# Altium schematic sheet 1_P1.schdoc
size 431 x 309 mm; Symbol: Sheet-Symbol_A3; Device: Sheet-Symbol_A3; Company: 嘉立创EDA; Version: V1.0; Page Size: A3; @Project Name: 辉光管_2024.2.16; @Page Count: 1; @Update Date: 2024-06-18; @Create Date: 2024-06-18; @Schematic Name: Schematic6; @Page No: 1; @Page Name: P1
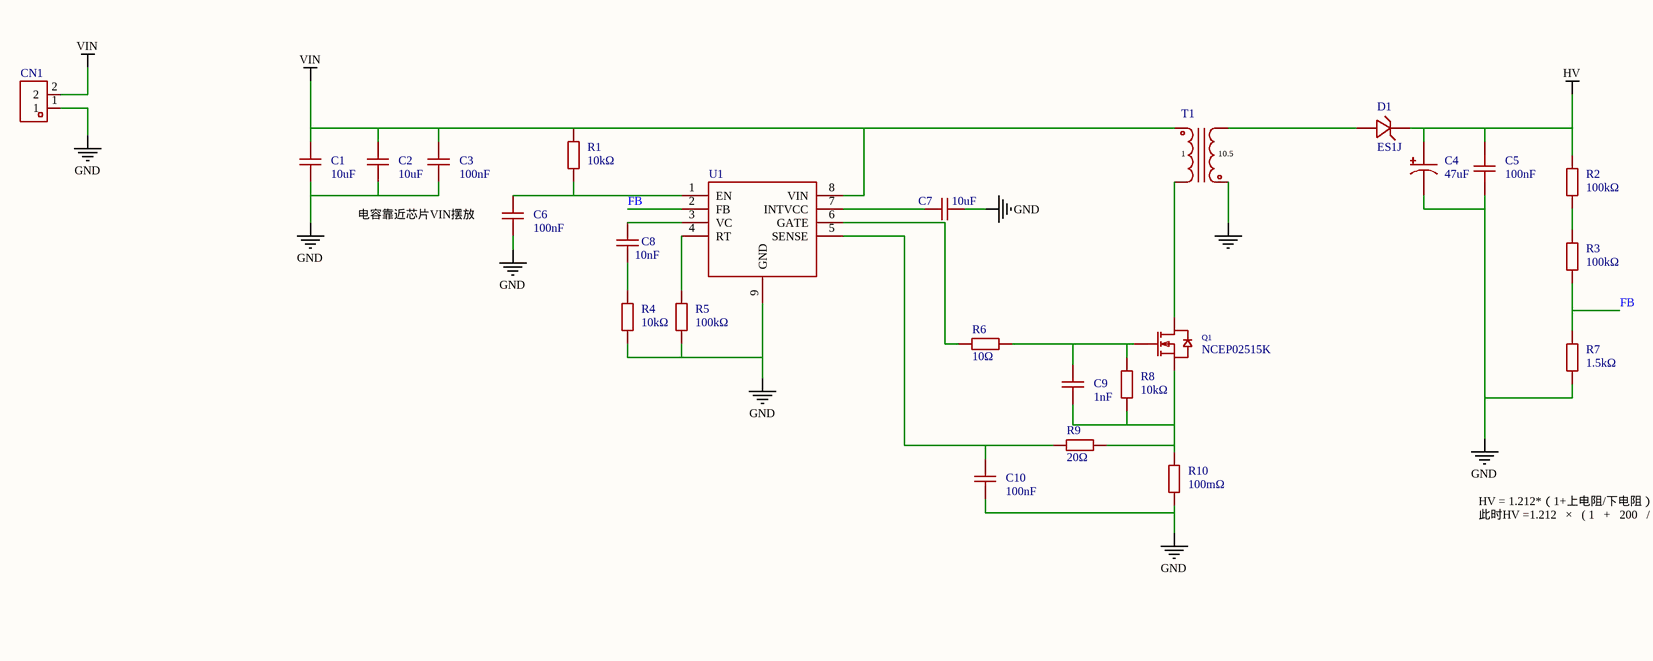
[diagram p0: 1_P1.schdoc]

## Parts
C1  10uF  [C0805]  (value not drawn)
C2  10uF  [C0805]  (value not drawn)
C3  100nF  [C0603]  (value not drawn)
C4  47uF  [CAP-TH_BD12.5-P5.00-D0.6-FD]  (value not drawn)
C5  100nF  [C1206]  (value not drawn)
C6  100nF  [C0603]  (value not drawn)
C7  10uF  [C0805]  (value not drawn)
C8  10nF  [C0603]  (value not drawn)
C9  1nF  [C0603]  (value not drawn)
C10  100nF  [C0603]  (value not drawn)
CN1  ZX-XH2.54-2PZZ  [CONN-TH_2P-P2.50_HX25003-2A]  (value not drawn)
D1  ES1J  [SMA_L4.4-W2.8-LS5.4-RD]  (value not drawn)
Q1  NCEP02515K  [TO-252-3_L6.6-W6.1-P4.58-LS10.1-BR-2]  (value not drawn)
R1  10kΩ  [R0603]  (value not drawn)
R2  100kΩ  [R1206]  (value not drawn)
R3  100kΩ  [R1206]  (value not drawn)
R4  10kΩ  [R0603]  (value not drawn)
R5  100kΩ  [R0603]  (value not drawn)
R6  10Ω  [R0603]  (value not drawn)
R7  1.5kΩ  [R0805]  (value not drawn)
R8  10kΩ  [R0603]  (value not drawn)
R9  20Ω  [R0603]  (value not drawn)
R10  100mΩ  [R1206]  (value not drawn)
T1  TTRN-060S-013-T  [TTRN-060S-013]  (value not drawn)
U1  ASP3756  [ESOP-8_L4.9-W3.9-P1.27-LS6.0-BL-EP4.2]  (value not drawn)

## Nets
GND: C1.1 C2.1 C3.1 C4.2 C5.1 C6.1 C7.2 C10.1 CN1.1 R4.1 R5.1 R7.1 R10.1 T1.3 U1.9(GND)
HV: C4.1 C5.2 D1.1(C) R2.1
VIN: C1.2 C2.2 C3.2 CN1.2 R1.2 T1.1 U1.8(VIN)
FB: R3.2 R7.2 U1.2(FB)
NetC6_2: C6.2 R1.1 U1.1(EN)
NetC7_1: C7.1 U1.7(INTVCC)
NetC8_1: C8.1 R4.2
NetC8_2: C8.2 U1.3(VC)
NetC9_1: C9.1 Q1.3(S) R8.1 R9.2 R10.2
NetC9_2: C9.2 Q1.1(G) R6.2 R8.2
NetC10_2: C10.2 R9.1 U1.5(SENSE)
NetD1_2: D1.2(A) T1.2
NetQ1_2: Q1.2(D) T1.5
NetR2_2: R2.2 R3.1
NetR5_2: R5.2 U1.4(RT)
NetR6_1: R6.1 U1.6(GATE)

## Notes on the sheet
- 电容靠近芯片VIN摆放
- HV = 1.212*（1+上电阻/下电阻）
  此时HV =1.212   ×   ( 1   +   200   /   1.5 ) = 162.712

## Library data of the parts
C1 C2 C7 = 0805X106K250NT: 容值:10uF;精度:±10%;额定电压:25V;材质(温度系数):X5R;; Manufacturer: FH(风华); Add into BOM: yes; Tolerance: ±10%; Voltage Rated: 25V; Temperature Coefficient: X5R
C3 C6 C10 = 0603B104K500NT: 容值:100nF;精度:±10%;额定电压:50V;材质(温度系数):X7R;; Manufacturer: FH(风华); Add into BOM: yes; Tolerance: ±10%; Voltage Rated: 50V; Temperature Coefficient: X7R
C4 = EGS2EM470W16OT: 容值:47uF;精度:±20%;额定电压:250V;纹波电流:-;等效串联电阻:-;; Manufacturer: AISHI(艾华集团); Add into BOM: yes; Tolerance: ±20%; Rated Voltage: 250V; φD: 12.5mm; L: 16mm; Lifetime @ Temp: 6000hrs@105℃
C5 = 1206B104K251NT_C2909525: 容值:100nF;精度:±10%;额定电压:250V;材质(温度系数):X7R;; Manufacturer: FH(风华); Add into BOM: yes; Tolerance: ±10%; Voltage Rated: 250V; Temperature Coefficient: X7R
C8 = 0603B103K500NT: 容值:10nF;精度:±10%;额定电压:50V;材质(温度系数):X7R;; Manufacturer: FH(风华); Add into BOM: yes; Tolerance: ±10%; Voltage Rated: 50V; Temperature Coefficient: X7R
C9 = CC0603KRX7R9BB102: 容值:1nF;精度:±10%;额定电压:50V;材质(温度系数):X7R;; Manufacturer: YAGEO(国巨); Add into BOM: yes; Tolerance: ±10%; Voltage Rated: 50V; Temperature Coefficient: X7R
CN1 = ZX-XH2.54-2PZZ: 插针结构:1x2P;间距:2.54mm;安装方式:直插;参考系列:XH;总PIN数:2P;排数:1;每排PIN数:2;行距:-;额定电流:3A;触头材质:黄铜;触头镀层:锡;工作温度范围:-25℃~+85℃;; Manufacturer: Megastar(兆星); Add into BOM: yes; Pins Structure: 1x2P; Pitch: 2.54mm; Reference Series: XH; Number of PINs Per Row: 2; Current Rating (Max): 3A
D1 = ES1J_C412438: 二极管配置:独立式;正向压降(Vf):1.7V@1A;直流反向耐压(Vr):600V;平均整流电流(Io):1A;反向恢复时间(trr):35ns;; Manufacturer: MDD; Symbol: ES1JG_C412438; Add into BOM: yes; Diode Configuration: 独立式; Reverse Voltage (Vr): 600V; Average Rectified Current (Io): 1A; Reverse Leakage Current: 5uA@600V; Reverse Recovery Time (trr): 35ns
Q1 = NCEP02515K: 类型:N沟道;漏源电压(Vdss):250V;连续漏极电流(Id):15A;功率(Pd):140W;导通电阻(RDS(on)@Vgs,Id):200mΩ@10V,15A;阈值电压(Vgs(th)@Id):3.5V@250uA;; Manufacturer: NCE(无锡新洁能); Add into BOM: yes; Type: N沟道; Drain Source Voltage (Vdss): 250V; Power Dissipation (Pd): 140W; Total Gate Charge (Qg@Vgs): 8.9nC@10V; Input Capacitance (Ciss@Vds): 475pF@125V; Reverse Transfer Capacitance (Crss@Vds): 1.2pF@125V
R1 R4 R8 = 0603WAF1002T5E: 电阻类型:厚膜电阻;阻值:10kΩ;精度:±1%;功率:100mW;; Manufacturer: UNI-ROYAL(厚声); Add into BOM: yes; Tolerance: ±1%; Power(Watts): 100mW; Temperature Coefficient: ±100ppm/℃; Overload Voltage (Max): 75V
R2 R3 = 1206W4F1003T5E: 电阻类型:厚膜电阻;阻值:100kΩ;精度:±1%;功率:250mW;最大工作电压:200V;温度系数:±100ppm/℃;; Manufacturer: UNI-ROYAL(厚声); Add into BOM: yes; Tolerance: ±1%; Power(Watts): 250mW; Overload Voltage (Max): 200V
R5 = 0603WAF1003T5E: 电阻类型:厚膜电阻;阻值:100kΩ;精度:±1%;功率:100mW;最大工作电压:75V;温度系数:±100ppm/℃;; Manufacturer: UNI-ROYAL(厚声); Add into BOM: yes; Tolerance: ±1%; Power(Watts): 100mW; Overload Voltage (Max): 75V
R6 = 0603WAF100JT5E: 电阻类型:厚膜电阻;阻值:10Ω;精度:±1%;功率:100mW;最大工作电压:75V;温度系数:±400ppm/℃;; Manufacturer: UNI-ROYAL(厚声); Add into BOM: yes; Tolerance: ±1%; Power(Watts): 100mW; Overload Voltage (Max): 75V
R7 = 0805W8F1501T5E: 电阻类型:厚膜电阻;阻值:1.5kΩ;精度:±1%;功率:125mW;最大工作电压:150V;温度系数:±100ppm/℃;; Manufacturer: UNI-ROYAL(厚声); Add into BOM: yes; Tolerance: ±1%; Power(Watts): 125mW; Overload Voltage (Max): 150V
R9 = 0603WAF200JT5E: 电阻类型:厚膜电阻;阻值:20Ω;精度:±1%;功率:100mW;最大工作电压:75V;温度系数:±100ppm/℃;; Manufacturer: UNI-ROYAL(厚声); Add into BOM: yes; Tolerance: ±1%; Power(Watts): 100mW; Overload Voltage (Max): 75V
R10 = 1206W4F100LT5E: 电阻类型:厚膜电阻;阻值:100mΩ;精度:±1%;功率:250mW;最大工作电压:200V;温度系数:±800ppm/℃;; Manufacturer: UNI-ROYAL(厚声); Add into BOM: yes; Tolerance: ±1%; Power(Watts): 250mW; Overload Voltage (Max): 200V
T1 = TTRN-060S-013-T: Pin Type: IN; Add into BOM: yes
U1 = ASP3756: Add into BOM: yes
